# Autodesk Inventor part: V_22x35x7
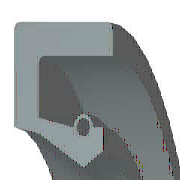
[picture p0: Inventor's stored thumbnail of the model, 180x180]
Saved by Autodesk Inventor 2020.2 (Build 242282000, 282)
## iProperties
Manager: www.cadconsulting.pl
Company: Fabian Stasiak CAD Consulting
Created: 2006-03
Part Number: V_22x35x7
Material: TS
Description: Pierścień uszczelniający 22x35x7-NBR
Vendor: Autodesk Inc.
Document SubType Name: Modeling
Standard: DIN 3760
Designer: F.Stasiak
Standards Organization: DIN
Language: pl-PL
Size Designation: A - 22 x 35 x 7 - NBR
Categories: <MemberInstance Version="R10.0.0"><Categories><Category DisplayName="Części wałów" InternalName="7f7aeb1f-a693-4053-b835-cee3144e0d98" Mnemonic="SHFT"><Category
Stock Number: PFP 1Z22357
Project: Przekładnia X51
Density: 1.06 g/cm^3
Appearance: Tworzywo sztuczne (czarne)
Author: F.Stasiak
Subject: Zbiór ćwiczeń. Autodesk Inventor 2020. Kurs podstawowy
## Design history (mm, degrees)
revolve "Bryła" stored, may be unused: angle "d17" = 90 deg
revolve "Sprężyna1" stored, may be unused: angle "d18" = 90 deg
node "Bryła1"
node "Korpusy bryłowe"
node "Korpusy powierzchniowe"
sketch "Szkic1"
  geometry: L1 (0, 17.5)-(7, 17.5); L2 (7, 17.5)-(7, 16.25); L3 (7, 16.25)-(1.75, 16.25); L4 (0, 17.5)-(0, 13.1); L5 (0, 13.1)-(1.75, 12.75); L6 (1.75, 12.75)-(4.9, 11); L7 (4.9, 11)-(0, 11); L8 (6.3, 11.875)-(6.3, 13.1); L9 (0, 0)-(9.586, 0) reference; L10 (4.9, 11)-(6.3, 11.875); L11 (0, 19.5)-(0, -1.5) reference; L12 (-0.959, 0)-(12.461, 0) reference; L13 (4.2, 13.1)-(1.75, 13.59); L14 (1.75, 13.59)-(1.75, 16.25); L15 (6.3, 13.1)-(5.6, 13.1); C1 r 0.455 at (4.9, 13.1); A1 r 0.7 centre (4.9, 13.1) between (5.6, 13.1) and (4.2, 13.1)
  constraints: 26 end point, 5 horizontal alignment, 4 perpendicular, 2 centre point, 2 collinear, 2 horizontal, 2 parallel, 2 point on circle, 2 point on line, 2 vertical alignment, 1 coincident
  dimensions: "d0" = 35 diameter of L1 L9 (= SD2); "d1" = 23.75 diameter of L8.start L9 (= ABDM); "d2" = 1.25 distance of L1.end L2.end (computed from SD); "d3" = 0.91 diameter of C1 (= SPDI); "d4" = 1.4 diameter of A1 (= SPDA); "d5" = 22 diameter of L6.end L9 (= NND); "d6" = 25.5 diameter of L5.end L9 (= TKDM); "d7" = 26.2 diameter of L4.end L9 (= HLDM); "d8" = 4.9 distance from line of C1.centre L4 (= SPDST); "d9" = 6.3 distance between parallel lines of L8 L4 (= SDI); "d10" = 7 distance between parallel lines of L2 L4 (= SWDT); "d12" = 1.75 distance between parallel lines of L14 L4 (= SD)
fillet "Zaokrąglenie1" dims "d11" = 0.3 (= RR)
other parameters: "SD2" = 35 [user parameter; used in 1 equation term], "SWDT" = 7 [user parameter; used in 1 equation term], "RR" = 0.3 [user parameter; used in 1 equation term], "SD" = 1.75 [user parameter; used in 2 equation terms], "NND" = 22 [user parameter; used in 1 equation term], "SPDA" = 1.4 [user parameter; used in 1 equation term], "SPDI" = 0.91 [user parameter; used in 1 equation term], "TKDM" = 25.5 [user parameter; used in 1 equation term], "HLDM" = 26.2 [user parameter; used in 1 equation term], "ABDM" = 23.75 [user parameter; used in 1 equation term], "SDI" = 6.3 [user parameter; used in 1 equation term], "SPDST" = 4.9 [user parameter; used in 1 equation term], "d13" = 0, "d14" = 0, "d15" = 0, "LAB" = 0.35 [user parameter]
